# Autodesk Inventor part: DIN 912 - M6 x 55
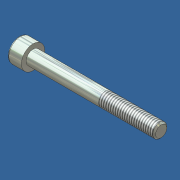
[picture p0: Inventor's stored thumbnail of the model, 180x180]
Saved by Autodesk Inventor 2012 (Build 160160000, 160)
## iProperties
IsCustomPart: 1
Created: 2006-02
Part Number: DIN 912 - M6 x 55
Material: Steel, Mild
Description: Cylinder Head Cap Screw
Document SubType Name: Modeling
Standard: DIN 912
Designer: Andy Moles
Standards Organization: DIN
Language: en-US
Size Designation: M6 x 55
Categories: <MemberInstance><Categories><Category DisplayName="Fasteners" InternalName="e4da775c-781d-43d5-af7c-5136215cf5a6" Mnemonic="FSTN"><Category DisplayName="Bolts"
Density: 1 g/cm^3
Author: Andy Moles
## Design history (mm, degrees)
workplane "Work Plane1"
revolve "Body" stored, may be unused: angle "d10" = 90 deg
sketch "Sketch2"
  geometry: L1 (0, -6)-(0, 8) reference; L2 (-6, 0)-(8, 0) reference; L3 (2.887, 0)-(1.443, -2.5); L4 (1.443, -2.5)-(-1.443, -2.5); L5 (-1.443, -2.5)-(-2.887, 0); L6 (-2.887, 0)-(-1.443, 2.5); L7 (-1.443, 2.5)-(1.443, 2.5); L8 (1.443, 2.5)-(2.887, 0); 2 further points
  constraints: 12 end point, 1 coincident, 1 horizontal alignment, 1 point on line, 12 other
extrude "Slot" join sketch "Sketch2" stored distance "d11" = 10; taper "d12" = 0 deg
body "Solid1"
fillet "Fillet1" dims "d17" = 0.6 (= RR)
feature "Thread" dims "d13" = 24 (= GEL), "d14" = 0
chamfer "Chamfer1" distance "d15" = 0.61345 (= -0.5 x SPD + 0.5 x GD); stored, may be unused: second distance "d16" = 0.61345 (= GUL), angle "d27" = 45 deg
sketch "Sketch1"
  geometry: L1 (-1.333, 0)-(55, 0); L2 (55, 0)-(55, 3); L3 (55, 3)-(31, 3); L4 (31, 3)-(30.386, 3); L5 (30.386, 3)-(0, 3); L6 (0, 3)-(0, 5); L7 (0, 5)-(-6, 5); L8 (-6, 5)-(-6, 2.887); L9 (-6, 2.887)-(-3, 2.887); L10 (-3, 2.887)-(-1.333, 0); L11 (-12.1, 0)-(73.3, 0) reference; L12 (0, -0.5)-(0, 6.5) reference; L13 (31, 3)-(0, 3)
  constraints: 22 end point, 6 parallel, 2 collinear, 2 perpendicular, 1 horizontal, 1 midpoint
  dimensions: "d1" = 24 distance from line of L3.end L2 (= GEL); "d2" = 0.61355 distance of L4.end L3.end (computed from GAL); "d3" = 6 distance between parallel lines of L8 L6 (= KOH); "d4" = 3 distance of L8.end L9.end (= INTI); "d5" = 60 deg angle of L10 L1; "d6" = 6 diameter of L3 L1 (= GD); "d7" = 6 diameter of L5 L1 (= BDM); "d8" = 5.7735 diameter of L9 L1 (= 1.1547 x SW); "d9" = 10 diameter of L7 L1 (= KOD); "d26" = 55 distance between parallel lines of L12 L2 (= NLG)
other parameters: "GD" = 6 (= NND) [user parameter; used in 2 equation terms], "NLG" = 55 [user parameter; used in 1 equation term], "GEL" = 24 [user parameter; used in 2 equation terms], "KOD" = 10 [user parameter; used in 1 equation term], "KOH" = 6 [user parameter; used in 2 equation terms], "INTI" = 3 [user parameter; used in 1 equation term], "GAL" = 0.61345 (= 0.61345 x PTC) [user parameter; used in 1 equation term], "GUL" = 0.61345 (= 0.61345 x PTC) [user parameter; used in 1 equation term], "BDM" = 6 (= NND) [user parameter; used in 1 equation term], "SW" = 5 [user parameter; used in 2 equation terms], "RR" = 0.6 (= 0.1 x KOH) [user parameter; used in 1 equation term], "SPD" = 4.7731 (= NND - 1.2269 x PTC) [user parameter; used in 1 equation term], "d19" = 0, "d28" = 0, "d29" = 0, "TOA" = 30 deg [user parameter], "GD1" = 4.7731 (= THREADDIA - 1.2269 x PTC) [user parameter], "THREADDIA" = 6 [user parameter; used in 1 equation term], "FAWI" = 45 deg [user parameter], "ANG" = 120 deg [user parameter], "PTC" = 1 [user parameter; used in 5 equation terms], "NND" = 6 [user parameter; used in 3 equation terms], "E0" = 5.775 (= 1.155 x SW) [user parameter]
